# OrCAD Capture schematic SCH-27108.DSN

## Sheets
1 TITLE PAGE: title: 1231X-MRB  (Navajo); rev: A2; company: Freescale Semiconductor; note: SCH-27108 PDF: SPF-27108; note: 6501 William Cannon Drive West; note: Austin, TX 78735-8598
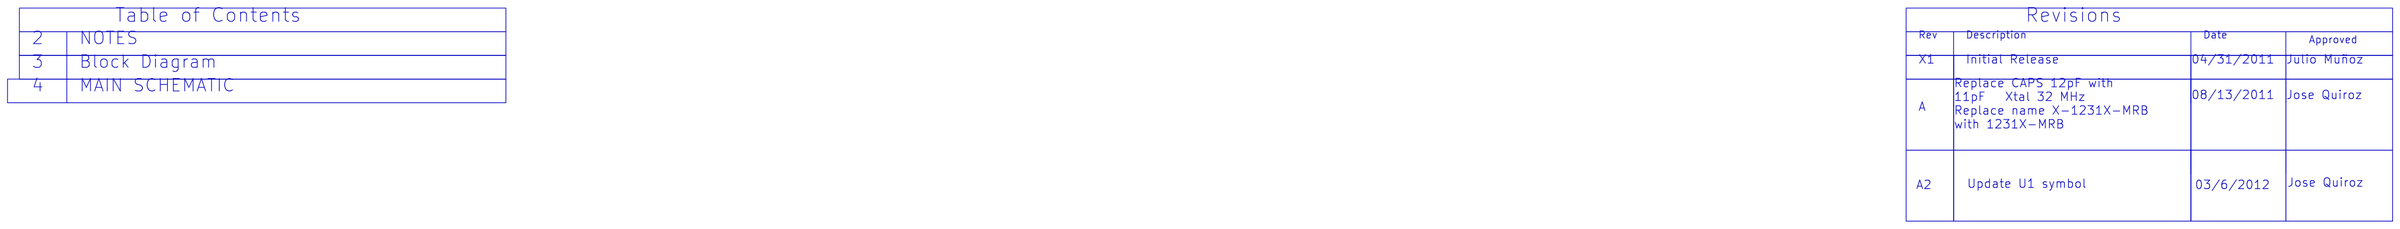
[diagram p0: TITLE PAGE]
2 NOTES
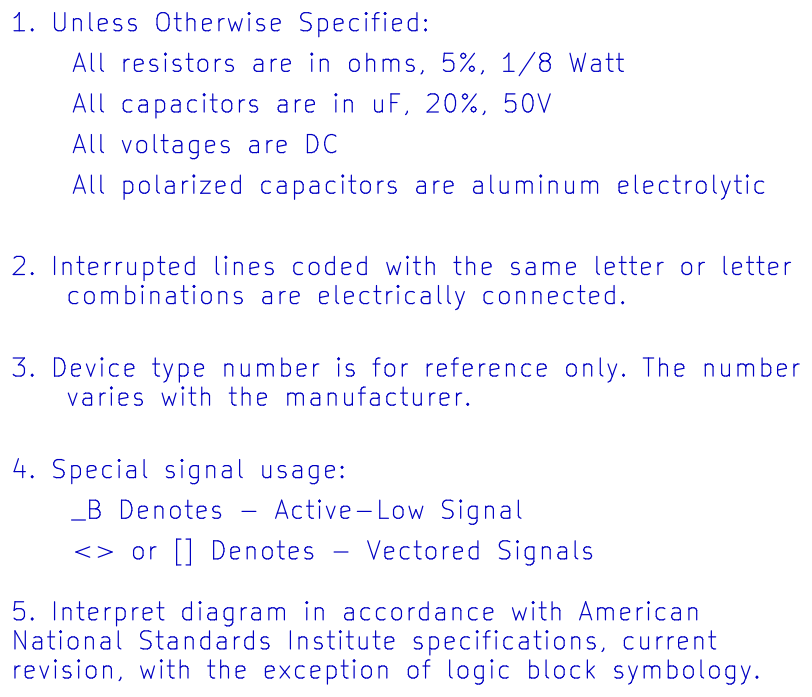
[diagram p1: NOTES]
3 Block Diagram
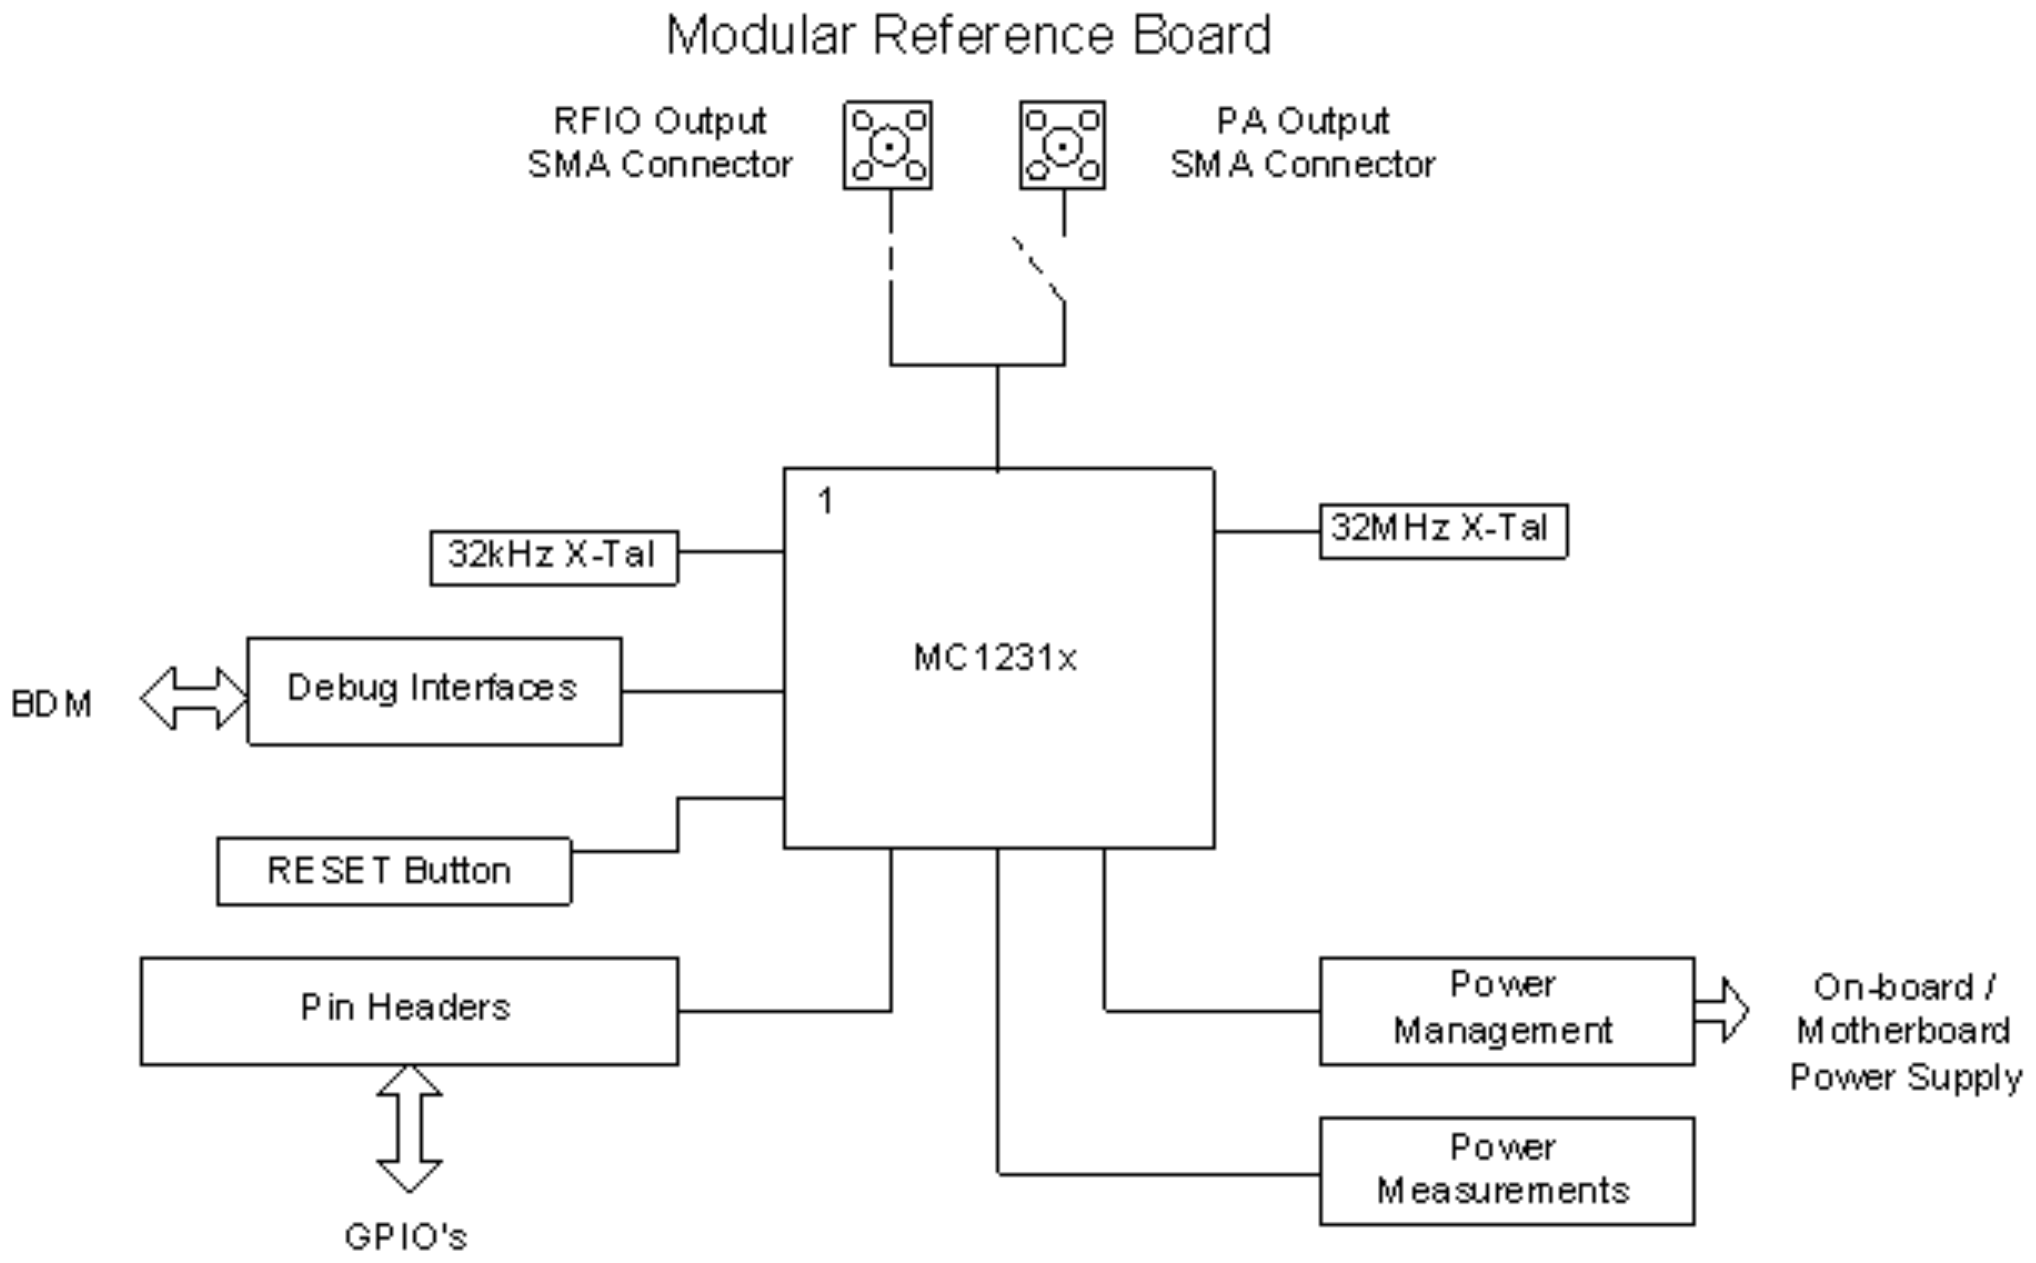
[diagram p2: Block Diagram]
4 MAIN SCHEMATIC: size C
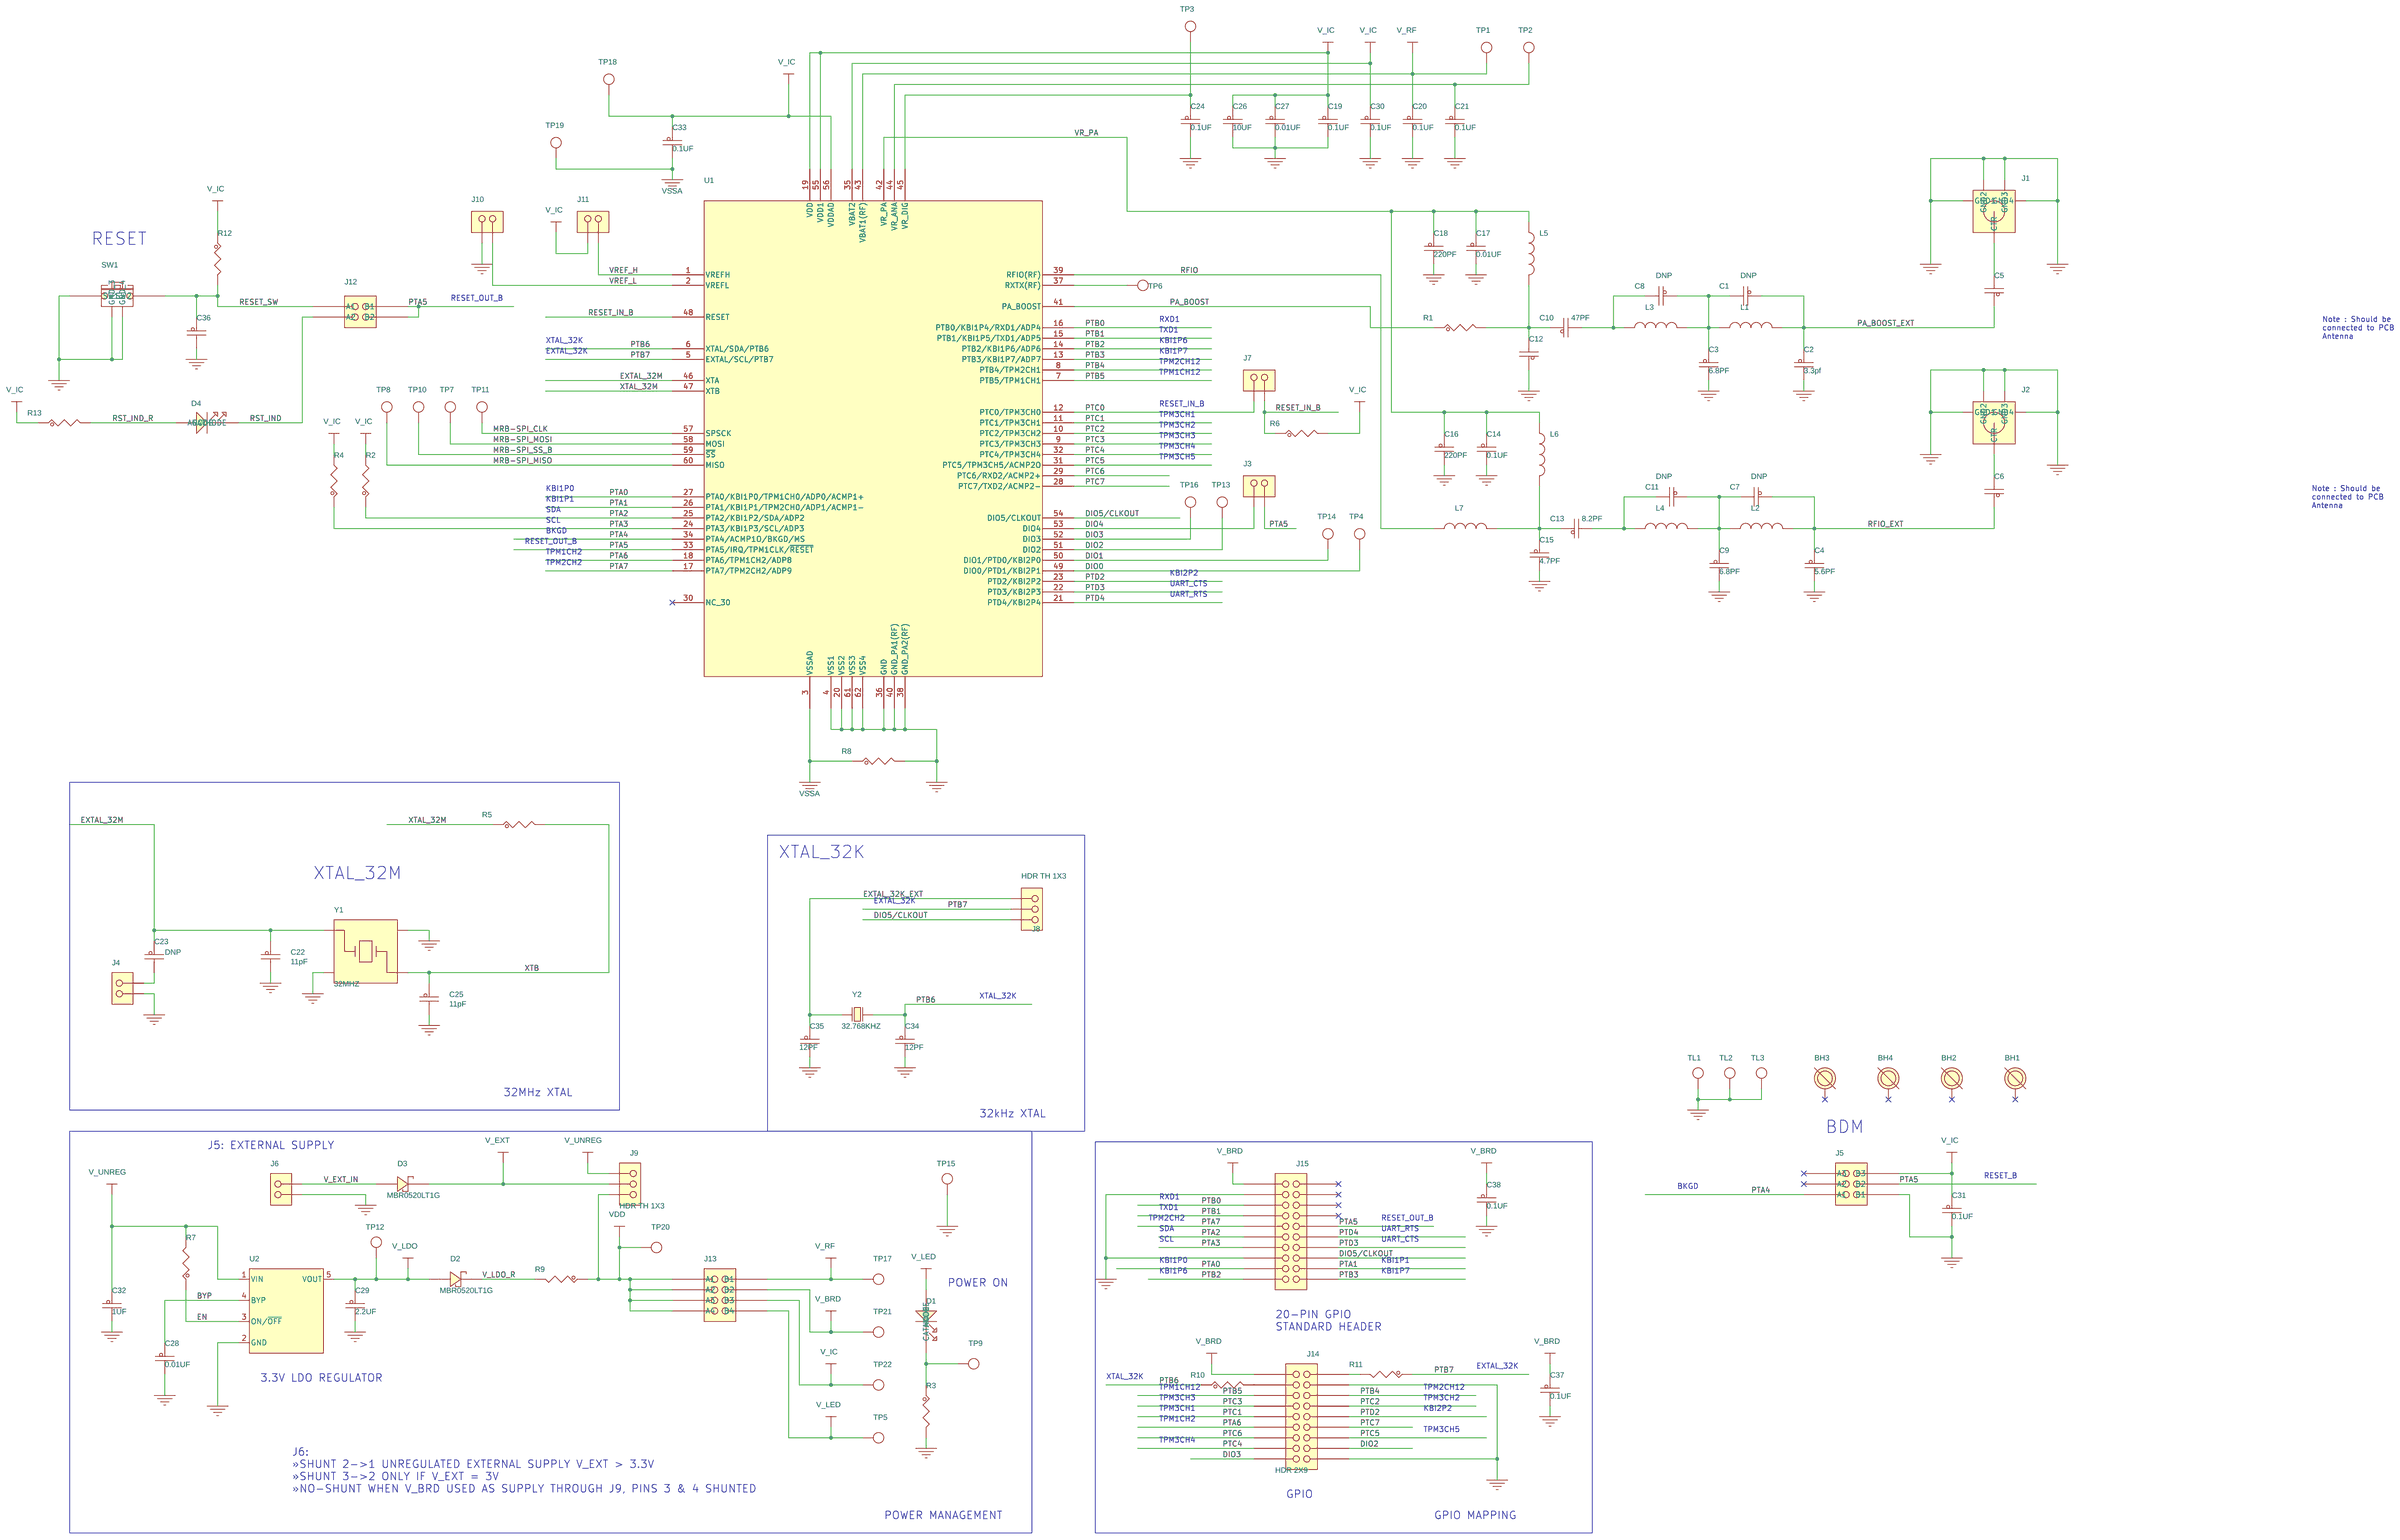
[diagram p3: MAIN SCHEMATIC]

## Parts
BH1  125  [MH125-160]
BH2  125  [MH125-160]
BH3  125  [MH125-160]
BH4  125  [MH125-160]
C1  10PF  [0402_CC]
C2  3.3pf  [0402_CC]
C3  6.8PF  [0402_CC]
C4  5.6PF  [0402_CC]
C5  10PF  [0402_CC]
C6  10PF  [0402_CC]
C7  10PF  [0402_CC]
C8  10PF  [0402_CC]
C9  6.8PF  [0402_CC]
C10  47PF  [0402_CC]
C11  10PF  [0402_CC]
C12  10PF  [0402_CC]
C13  8.2PF  [0402_CC]
C14  0.1UF  [0402_CC]
C15  4.7PF  [0402_CC]
C16  220PF  [0402_CC]
C17  0.01UF  [0402_CC]
C18  220PF  [0402_CC]
C19  0.1UF  [CC0402_25]
C20  0.1UF  [CC0402_25]
C21  0.1UF  [CC0402_25]
C22  11pF  [CC0402_25]
C23  10PF  [0402_CC]
C24  0.1UF  [CC0402_25]
C25  11pF  [CC0402_25]
C26  10UF  [CC0805_OV]
C27  0.01UF  [CC0402_25]
C28  0.01UF  [CC0402_25]
C29  2.2UF  [CC0603_OV]
C30  0.1UF  [CC0402_25]
C31  0.1UF  [CC0402_25]
C32  1UF  [CC0603_OV]
C33  0.1UF  [CC0402_25]
C34  12PF  [CC0402_25]
C35  12PF  [CC0402_25]
C36  1000pF  [CC0402_25]
C37  0.1UF  [CC0402_25]
C38  0.1UF  [CC0402_25]
D1  GREEN  [led2_0805]
D2  MBR0520LT1G  [SOD123]
D3  MBR0520LT1G  [SOD123]
D4  RED  [led2_0805]
J1  CON_1_SMA  [CON_SMA_8363]
J2  CON_1_SMA  [CON_SMA_8363]
J3  HDR 1X2  [hdr102]
J4  HDR 1X2  [hdr102]
J5  HDR 2X3  [HDR203]
J6  HDR 1X2  [hdr102]
J7  HDR 1X2  [hdr102]
J8  HDR TH 1X3  [HDR103]
J9  HDR TH 1X3  [HDR103]
J10  HDR 1X2  [hdr102]
J11  HDR 1X2  [hdr102]
J12  961204-6404-AR  [hdr202_100_th]
J13  HDR_2X4  [HDR2X4]
J14  HDR 2X9  [hdr_9x2_tsw_mirrored]
J15  HDR_10X2  [hdr210_mirrored]
L1  5.6NH  [0402_CC]
L2  6.8nH  [0402_CC]
L3  5.6NH  [0402_CC]
L4  6.8nH  [0402_CC]
L5  33nH  [0402_CC]
L6  33nH  [0402_CC]
L7  0.0039UH  [0402_CC]
R1  0  [0402_CC]
R2  4.7K  [RC0603_OV]
R3  330  [RC0402_25]
R4  4.7K  [RC0603_OV]
R5  0  [RC0603_OV]
R6  10.0K  [RC0402_25]
R7  0  [RC0603_OV]
R8  0  [RC0603_OV]
R9  0  [RC0603_OV]
R10  0  [RC0603_OV]
R11  0  [RC0603_OV]
R12  15K  [RC0402_25]
R13  422.0  [RC0603_OV]
SW1  SW_MOM  [sw_tact_skqy]
TL1  TESTLOOP  [testpoint_135_070mil]
TL2  TESTLOOP  [testpoint_135_070mil]
TL3  TESTLOOP  [testpoint_135_070mil]
TP1  TPAD_040  [TPAD_040]
TP2  TPAD_040  [TPAD_040]
TP3  TPAD_040  [TPAD_040]
TP4  TPAD_040  [TPAD_040]
TP5  TPAD_040  [TPAD_040]
TP6  TPAD_040  [TPAD_040]
TP7  TPAD_040  [TPAD_040]
TP8  TPAD_040  [TPAD_040]
TP9  TPAD_040  [TPAD_040]
TP10  TPAD_040  [TPAD_040]
TP11  TPAD_040  [TPAD_040]
TP12  TPAD_040  [TPAD_040]
TP13  TPAD_040  [TPAD_040]
TP14  TPAD_040  [TPAD_040]
TP15  TPAD_040  [TPAD_040]
TP16  TPAD_040  [TPAD_040]
TP17  TPAD_040  [TPAD_040]
TP18  TPAD_040  [TPAD_040]
TP19  TPAD_040  [TPAD_040]
TP20  TPAD_040  [TPAD_040]
TP21  TPAD_040  [TPAD_040]
TP22  TPAD_040  [TPAD_040]
U1  MC12311  [LGA60_0P5_8X8]
U2  LP2985AIM5-3.3  [SOT-23-5]
Y1  32MHZ  [xtlosc4_3p2x2p5mm_sm]
Y2  32.768KHZ  [XTAL2-3p2x1p5-SM]

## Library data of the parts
BH1-BH4 = MOUNT_HOLE: NON-PLATED MOUNTING HOLE 125 DRILL / 160 KEEPOUT NO PART TO ORDER; AGILE_PN: 510-75297; CAD_APPROVED: Yes; HEIGHT: 0.1 MM; ROHS: Yes
C1 C7 C8 C11 C23 = CAP_NP: CAP CER 10PF 50V 5% C0G 0402; AGILE_PN: 150-75265; ASSY_OPT: DNP; CAD_APPROVED: YES; FPLIST: CC0402_25,CC0402_HD,0402_CC; HEIGHT: 0.635MM; MFG_NAME01: AVX; MFG_PN01: 04025A100JAT2A; ROHS: Yes; TOL: 5%; Tolerance: 5%
C2 = CAP_NP: CAP CER 3.3PF 25V 0.1PF -- 0402; AGILE_PN: 150-78484; CAD_APPROVED: Yes; FPLIST: CC0402_25,CC0402_HD,0402_CC; HEIGHT: 0.5MM; MFG_NAME01: AVX; MFG_PN01: 04023J3R3BBSTR; ROHS: Yes
C3 C9 = CAP_NP: CAP CER 6.8PF 50V 0.5PF C0G 0402; AGILE_PN: 150-30300; CAD_APPROVED: Yes; FPLIST: CC0402_25,CC0402_HD,0402_CC; HEIGHT: 0.55MM; MFG_NAME01: MURATA; MFG_PN01: GRM1555C1H6R8DZ01J; ROHS: Yes; Tolerance: 0.5PF %
C4 = CAP_NP: CAP CER 5.6PF 50V +/-0.25PF C0G CC0402; AGILE_PN: 150-75521; CAD_APPROVED: Yes; FPLIST: CC0402_25,CC0402_HD,0402_CC; HEIGHT: 0.55MM; MFG_NAME01: MURATA; MFG_PN01: GJM1555C1H5R6CB01D; ROHS: Yes; Tolerance: 0.25PF
C5 C6 C12 = CAP_NP: CAP CER 10PF 50V 5% C0G 0402; AGILE_PN: 150-75265; CAD_APPROVED: YES; FPLIST: CC0402_25,CC0402_HD,0402_CC; HEIGHT: 0.635MM; MFG_NAME01: AVX; MFG_PN01: 04025A100JAT2A; ROHS: Yes; TOL: 5%; Tolerance: 5%
C10 = CAP_NP: CAP CER 47PF 50V 5% C0G 0402; AGILE_PN: 150-75169; CAD_APPROVED: Yes; FPLIST: CC0402_25,CC0402_HD,0402_CC; HEIGHT: 0.64 MM; MFG_NAME01: CAL-CHIP; MFG_PN01: GMC04CG470J50NT-LF; ROHS: Yes; Tolerance: 5%
C13 = CAP_NP: CAP CER 8.2PF 50V 0.25PF C0G 0402; AGILE_PN: 150-30084; CAD_APPROVED: Yes; FPLIST: CC0402_25,CC0402_HD,0402_CC; HEIGHT: 0.56MM; MFG_NAME01: AVX; MFG_PN01: 04025A8R2CAT2A; ROHS: Yes; Tolerance: 0.25PF
C14 C19-C21 C24 C30 C31 C33 C37 C38 = CAP_NP: CAP CER 0.1UF 16V 10% X7R 0402; AGILE_PN: 150-75182; CAD_APPROVED: Yes; FPLIST: CC0402_25,CC0402_HD,0402_CC; HEIGHT: 0.635MM; MFG_NAME01: KEMET; MFG_PN01: C0402C104K4RAC; ROHS: Yes; Tolerance: 10%
C15 = CAP_NP: CAP CER 4.7PF 50V 0.25PF C0G 0402; AGILE_PN: 150-76335; CAD_APPROVED: Yes; FPLIST: CC0402_25,CC0402_HD,0402_CC; HEIGHT: 0.55MM; MFG_NAME01: MURATA; MFG_PN01: GRM1555C1H4R7CA01D; ROHS: Yes; Tolerance: 0.25pF
C16 C18 = CAP_NP: CAP CER 220PF 50V 5% C0G 0402; AGILE_PN: 150-30297; CAD_APPROVED: Yes; FPLIST: CC0402_25,CC0402_HD,0402_CC; HEIGHT: 0.55MM; MFG_NAME01: KEMET; MFG_PN01: C0402C221J5GAC; ROHS: Yes; Tolerance: 5%
C17 C27 C28 = CAP_NP: CAP CER 0.01UF 50V 10% X7R 0402; AGILE_PN: 150-30114; CAD_APPROVED: Yes; FPLIST: CC0402_25,CC0402_HD,0402_CC; HEIGHT: 0.74 MM; MFG_NAME01: MURATA; MFG_PN01: GCM155R71H103KA55D; ROHS: Yes; Tolerance: 10%
C22 C25 = CAP_NP: CAP CER 11pF 50V 5% C0G 0402; AGILE_PN: 150-78794; CAD_APPROVED: Yes; FPLIST: CC0402_25,CC0402_HD,0402_CC; HEIGHT: 0.55MM; MFG_NAME01: TDK; MFG_PN01: C1005C0G1H110J; ROHS: Yes; Tolerance: 5%
C26 = CAP_NP: CAP CER 10UF 10V 10% X5R 0805; AGILE_PN: 150-75204; CAD_APPROVED: Yes; FPLIST: CC0805_OV,CC0805,0805_CC; HEIGHT: 1.6MM; MFG_NAME01: MURATA; MFG_PN01: GRM21BR61A106KE19_; ROHS: Yes; Tolerance: 10%
C29 = CAP_NP: CAP CER 2.2UF 10V 10% X7R 0603; AGILE_PN: 150-78564; CAD_APPROVED: Yes; FPLIST: CC0603_OV,CC0603,0603_CC; HEIGHT: 1.25MM; MFG_NAME01: MURATA; MFG_PN01: GRM188R71A225KE15D; ROHS: Yes; Tolerance: 10%
C32 = CAP_NP: CAP CER 1.0UF 10V 10% X7R 0603; AGILE_PN: 150-78462; CAD_APPROVED: Yes; FPLIST: CC0603_OV,CC0603,0603_CC; HEIGHT: 0.9MM; MFG_NAME01: MURATA; MFG_PN01: GRM188R71A105KA61D; ROHS: Yes; Tolerance: 10%
C34 C35 = CAP_NP: CAP CER 12PF 50V 5% C0G 0402; AGILE_PN: 150-75680; CAD_APPROVED: Yes; FPLIST: CC0402_25,CC0402_HD,0402_CC; HEIGHT: 0.55MM; MFG_NAME01: MURATA; MFG_PN01: GRM1555C1H120JZ01D; ROHS: Yes; Tolerance: 5%
C36 = CAP_NP: CAP CER 1000PF 50V 5% C0G 0402; AGILE_PN: 150-76334; CAD_APPROVED: Yes; FPLIST: CC0402_25,CC0402_HD,0402_CC; HEIGHT: 0.55MM; MFG_NAME01: MURATA; MFG_PN01: GRM1555C1H102JA01D; ROHS: Yes; Tolerance: 5%
D1 = LED: LED GRN SGL 30MA SMT 0805; AGILE_PN: 370-76462; CAD_APPROVED: Yes; HEIGHT: 0.9MM; MFG_NAME01: LITE ON; MFG_PN01: LTST-C171KGKT; ROHS: Yes
D2 D3 = DIODE_SCHTKY: DIODE SCH 0.5A 20V SOD-123; AGILE_PN: 480-75176; CAD_APPROVED: Yes; HEIGHT: 1.45MM; MFG_NAME01: ON SEMICONDUCTOR; ROHS: Yes
D4 = LED: LED RED CLEAR SGL 30MA SMT 0805; AGILE_PN: 370-76461; CAD_APPROVED: Yes; HEIGHT: 0.9MM; MFG_NAME01: LITE ON; MFG_PN01: LTST-C171KRKT; ROHS: Yes
J1 J2 = CON5_SMA_MMCX: CON 1 COAX SMA SKT TH -- 376H AU; AGILE_PN: 210-75870; CAD_APPROVED: Yes; HEIGHT: 9.55MM; MFG_NAME01: SAMTEC; MFG_PN01: SMA-J-P-H-ST-TH1; ROHS: Yes
J3 J4 J6 J7 J10 J11 = CONN_HDR_2X1: HDR 1X2 TH 100MIL SP 330H SN 115L; AGILE_PN: 210-76752; CAD_APPROVED: Yes; HEIGHT: 8.58MM; MFG_NAME01: Samtec; MFG_PN01: TSW-102-23-T-S; ROHS: Yes
J5 = CONN_HDR_3X2: HDR 2X3 TH 100MIL CTR 335H AU 95L; AGILE_PN: 210-75698; CAD_APPROVED: Yes; HEIGHT: 8.5MM; MFG_NAME01: SAMTEC; MFG_PN01: TSW-103-07-S-D; ROHS: Yes
J8 J9 = CONN_HDR_3X1: HDR 1X3 TH 100MIL SP 339H AU 100L; AGILE_PN: 210-75726; CAD_APPROVED: Yes; HEIGHT: 8.65MM; MFG_NAME01: SAMTEC; MFG_PN01: TSW-103-07-G-S; ROHS: Yes
J12 = CONN_HDR_2X2: HDR 2X2 TH 100MIL CTR 323H AU 130L; AGILE_PN: 210-79741; CAD_APPROVED: Yes; HEIGHT: 8.2MM; MFG_NAME01: 3M; ROHS: Yes
J13 = CONN_HDR_4X2: HDR 2X4 TH 100MIL CTR 330H AU 100L; AGILE_PN: 210-75541; CAD_APPROVED: Yes; HEIGHT: 8.6MM; MFG_NAME01: SAMTEC; MFG_PN01: TSW-104-07-S-D; ROHS: Yes
J14 = CONN_HDR_9X2: HDR 2X9 TH 100MIL CTR 330H AU; AGILE_PN: 210-11415-09; CAD_APPROVED: Yes; FPLIST: hdr_9x2_tsw,hdr_9x2_tsw_mirrored; HEIGHT: 8.6MM; MFG_NAME01: SAMTEC; MFG_PN01: TSW-109-07-S-D; ROHS: Yes
J15 = CONN_HDR_10X2: HDR 2X10 TH 100MIL CTR 330H AU 100L; AGILE_PN: 210-76001; CAD_APPROVED: Yes; FPLIST: hdr210,hdr210_mirrored; HEIGHT: 8.71 MM; MFG_NAME01: SAMTEC; MFG_PN01: TSW-110-07-S-D; ROHS: Yes
L1 L3 = INDUCTOR: IND -- 0.0056UH@100MHZ 300MA 0402; AGILE_PN: 180-75101; CAD_APPROVED: Yes; FPLIST: IND_0402,0402_CC; HEIGHT: 0.55MM; MFG_NAME01: TOKO INC.; MFG_PN01: LL1005-FHL5N6S; ROHS: Yes; Tolerance: 0.3NH
L2 L4 = INDUCTOR: IND -- 0.0068UH@100MHZ 400MA 5% 0402; AGILE_PN: 180-75396; CAD_APPROVED: Yes; FPLIST: IND_0402,0402_CC; HEIGHT: 0.55 MM; MFG_NAME01: TOKO INC.; MFG_PN01: LL1005-FHL6N8J; ROHS: Yes; Tolerance: 5%
L5 L6 = INDUCTOR: IND -- 0.033UH@100MHZ 200MA 5% 0402; AGILE_PN: 180-75099; CAD_APPROVED: YES; FPLIST: IND_0402,0402_CC; HEIGHT: 0.55MM; MFG_NAME01: TOKO INC.; MFG_PN01: LL1005-FHL33NJ; ROHS: Yes; Tolerance: 5%
L7 = INDUCTOR: IND -- 0.0039UH@100MHZ 300MA +/-0.3NH 0402; AGILE_PN: 180-30073; CAD_APPROVED: Yes; FPLIST: IND_0402,0402_CC; HEIGHT: 0.60mm; MFG_NAME01: MURATA; MFG_PN01: LQG15HN3N9S02D; ROHS: Yes
R1 = RES: RES MF ZERO OHM 1/10W -- 0402; AGILE_PN: 470-79965; CAD_APPROVED: Yes; FPLIST: RC0402_25,RC0402_HD,RC0402_X2,0402_CC; MFG_NAME01: Panasonic; MFG_PN01: ERJ-2GE0R00X; ROHS: Yes
R2 R4 = RES: RES MF 4.7K 1/10W 5% 0603; AGILE_PN: 470-75414; CAD_APPROVED: Yes; FPLIST: RC0603_OV,RC0603,0603_CC; MFG_NAME01: VISHAY INTERTECHNOLOGY; MFG_PN01: CRCW06034K70JNEA; ROHS: Yes; Tolerance: 5%
R3 = RES: RES MF 330 OHM 1/16W 5% 0402; AGILE_PN: 470-75613; CAD_APPROVED: Yes; FPLIST: RC0402_25,RC0402_HD,0402_CC; MFG_NAME01: VISHAY INTERTECHNOLOGY; MFG_PN01: CRCW0402330RJNED; ROHS: Yes; Tolerance: 5%
R5 R7-R11 = RES: RES MF ZERO OHM 1/10W -- 0603; AGILE_PN: 470-75407; CAD_APPROVED: Yes; FPLIST: RC0603_OV,RC0603,R603-X2,0603_CC; MFG_NAME01: VISHAY INTERTECHNOLOGY; MFG_PN01: CRCW06030000Z0EA; ROHS: Yes; Tolerance: 1%
R6 = RES: RES MF 10.0K 1/16W 1% 0402; AGILE_PN: 470-75416; CAD_APPROVED: Yes; FPLIST: RC0603_OV,RC0603,0603_CC; MFG_NAME01: VISHAY INTERTECHNOLOGY; MFG_PN01: CRCW040210K0FKED; ROHS: Yes; Tolerance: 1%
R12 = RES: RES MF 15K 1/16W 5% 0402; AGILE_PN: 470-30313; CAD_APPROVED: Yes; FPLIST: RC0402_25,RC0402_HD,0402_CC; HEIGHT: 0.41mm; MFG_NAME01: VISHAY INTERTECHNOLOGY; MFG_PN01: CRCW040215K0JNED; ROHS: Yes; TOL: 5%; Tolerance: %5
R13 = RES: RES MF 422 OHM  1/10W 1% 0603; AGILE_PN: 470-77949; CAD_APPROVED: Yes; FPLIST: RC0603_OV,RC0603,0603_CC; MFG_NAME01: YAGEO AMERICA; MFG_PN01: RC0603FR-07422RL; ROHS: Yes; Tolerance: 1%
SW1 = SW2_STM151: SW SPST MOM PB 50MA 12V SMT; AGILE_PN: 510-77653; CAD_APPROVED: Yes; HEIGHT: 2.5MM; MFG_NAME01: ALPS ELECTRIC (USA) INC.; MFG_PN01: SKQYPDE010; ROHS: Yes
TL1-TL3 = TestLoop: TEST POINT PAD SIZE 3.4MM X 1.8MM SMT; AGILE_PN: 211-75906; CAD_APPROVED: Yes; FPLIST: testpoint_135_070mil,testpoint_110_045mil,testpoint_125x40milmod; HEIGHT: 1.53 MM; MFG_NAME01: KEYSTONE ELECTRONICS; MFG_PN01: 5015; ROHS: Yes
TP1-TP22 = TestLoop: TEST POINT PAD 40MIL DIA SMT, NO PART TO ORDER; AGILE_PN: 211-76643; CAD_APPROVED: Yes; HEIGHT: 0.1MM; MFG_NAME01: NOTACOMPONENT; MFG_PN01: NOTACOMPONENT; ROHS: Yes
U1 = MC12311_LGA_60P: IC MCU 8BIT 32KB FLASH 2KB RAM 50MHZ 1.8-3.6V LGA60; AGILE_PN: 344-01203; CAD_APPROVED: Yes; HEIGHT: 0.98MM; MFG_NAME01: Freescale Semiconductor; MFG_PN01: MC12311CHN; ROHS: Yes
U2 = LP2992X_5P: IC VREG LDO 3.3V 150MA 3.8-16V SOT-23-5; AGILE_PN: 312-79597; CAD_APPROVED: Yes; HEIGHT: 1.22 MM; MFG_NAME01: NATIONAL SEMICONDUCTOR; MFG_PN01: LP2985AIM5-3.3/NOPB; ROHS: Yes
Y1 = XTAL_13Y: XTAL 32MHZ 9PF -- SMT 3.2X2.5MM; AGILE_PN: 230-77690; CAD_APPROVED: Yes; HEIGHT: 0.8MM; MFG_NAME01: NDK; MFG_PN01: EXS00A-CS02368; ROHS: Yes
Y2 = CRYSTAL: XTAL 32.768KHZ SMT ROHS COMPLIANT; AGILE_PN: 230-76374; CAD_APPROVED: Yes; HEIGHT: 0.9MM; MFG_NAME01: EPSON ELECTRONICS; MFG_PN01: FC-135 32.7680KA-A3; ROHS: Yes

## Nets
GND: C2.2 C3.2 C4.2 C9.2 C12.1 C14.2 C15.2 C16.2 C17.2 C18.2 C19.2 C20.2 C21.2 C22.2 C24.2 C25.2 C26.2 C27.2 C28.2 C29.2 C30.2 C31.2 C32.2 C34.2 C35.2 C36.2 C37.2 C38.2 J1.2(GND1) J1.3(GND2) J1.4(GND3) J1.5(GND4) J2.2(GND1) J2.3(GND2) J2.4(GND3) J2.5(GND4) J4.2 J5.2(B1) J6.2 J10.2 J14.4 J14.18 J15.3 J15.15 R3.2 R8.2 SW1.1(SW1) SW1.3(GND) SW1.4(GND) TL1.1(Pin1) TL2.1(Pin1) TL3.1(Pin1) TP15.1(Pin1) U1.4(VSS1) U1.20(VSS2) U1.36(GND) U1.38(GND_PA2(RF)) U1.40(GND_PA1(RF)) U1.61(VSS3) U1.62(VSS4) U2.2(GND) Y1.2 Y1.4
VDD: J9.3 J13.1(A1) J13.3(A2) J13.5(A3) J13.7(A4) R9.1 TP20.1(Pin1)
VSSA: C33.2 R8.1 TP19.1(Pin1) U1.3(VSSAD)
BYP: C28.1 U2.4(BYP)
DIO0: TP4.1(Pin1) U1.49(DIO0/PTD1/KBI2P1)
DIO1: TP14.1(Pin1) U1.50(DIO1/PTD0/KBI2P0)
DIO2: J14.16 TP13.1(Pin1) U1.51(DIO2)
DIO3: J14.17 TP16.1(Pin1) U1.52(DIO3)
DIO4: J3.2 U1.53(DIO4)
DIO5/CLKOUT: J8.1 J15.16 U1.54(DIO5/CLKOUT)
EN: R7.1 U2.3(ON/~{OFF})
EXTAL_32K_EXT: C35.1 J8.3 Y2.1
EXTAL_32M: C22.1 C23.1 U1.46(XTA) Y1.1
MRB-SPI_CLK: TP11.1(Pin1) U1.57(SPSCK)
MRB-SPI_MISO: TP8.1(Pin1) U1.60(MISO)
MRB-SPI_MOSI: TP7.1(Pin1) U1.58(MOSI)
MRB-SPI_SS_B: TP10.1(Pin1) U1.59(~{SS})
PA_BOOST: R1.1 U1.41(PA_BOOST)
PA_BOOST_EXT: C1.1 C2.1 C5.1 L1.2
PTA0: J15.17 U1.27(PTA0/KBI1P0/TPM1CH0/ADP0/ACMP1+)
PTA1: J15.18 U1.26(PTA1/KBI1P1/TPM2CH0/ADP1/ACMP1-)
PTA2: J15.11 R2.1 U1.25(PTA2/KBI1P2/SDA/ADP2)
PTA3: J15.13 R4.1 U1.24(PTA3/KBI1P3/SCL/ADP3)
PTA4: J5.1(A1) U1.34(PTA4/ACMP1O/BKGD/MS)
PTA5: J3.1 J5.4(B2) J12.2(B1) J12.4(B2) J15.10 U1.33(PTA5/IRQ/TPM1CLK/~{RESET})
PTA6: J14.11 U1.18(PTA6/TPM1CH2/ADP8)
PTA7: J15.9 U1.17(PTA7/TPM2CH2/ADP9)
PTB0: J15.5 U1.16(PTB0/KBI1P4/RXD1/ADP4)
PTB1: J15.7 U1.15(PTB1/KBI1P5/TXD1/ADP5)
PTB2: J15.19 U1.14(PTB2/KBI1P6/ADP6)
PTB3: J15.20 U1.13(PTB3/KBI1P7/ADP7)
PTB4: J14.6 U1.8(PTB4/TPM2CH1)
PTB5: J14.5 U1.7(PTB5/TPM1CH1)
PTB6: C34.1 R10.1 U1.6(XTAL/SDA/PTB6) Y2.2
PTB7: J8.2 R11.1 U1.5(EXTAL/SCL/PTB7)
PTC0: J7.2 U1.12(PTC0/TPM3CH0)
PTC1: J14.9 U1.11(PTC1/TPM3CH1)
PTC2: J14.8 U1.10(PTC2/TPM3CH2)
PTC3: J14.7 U1.9(PTC3/TPM3CH3)
PTC4: J14.15 U1.32(PTC4/TPM3CH4)
PTC5: J14.14 U1.31(PTC5/TPM3CH5/ACMP2O)
PTC6: J14.13 U1.29(PTC6/RXD2/ACMP2+)
PTC7: J14.12 U1.28(PTC7/TXD2/ACMP2-)
PTD2: J14.10 U1.23(PTD2/KBI2P2)
PTD3: J15.14 U1.22(PTD3/KBI2P3)
PTD4: J15.12 U1.21(PTD4/KBI2P4)
RESET_IN_B: J7.1 R6.1 U1.48(RESET)
RESET_SW: C36.1 J12.1(A1) R12.2 SW1.2(SW2)
RFIO: L7.1 U1.39(RFIO(RF))
RFIO_EXT: C4.1 C6.1 C7.1 L2.2
RST_IND: D4.C(CATHODE) J12.3(A2)
RST_IND_R: D4.A(ANODE) R13.2
V_BRD: C37.1 C38.1 J13.4(B2) J14.1 J15.1 TP21.1(Pin1)
V_EXT: D3.C J9.2
V_EXT_IN: D3.A J6.1
V_IC: C19.1 C26.1 C27.1 C30.1 C31.1 C33.1 J5.6(B3) J11.2 J13.6(B3) R2.2 R4.2 R6.2 R12.1 R13.1 TP18.1(Pin1) TP22.1(Pin1) U1.19(VDD) U1.35(VBAT2) U1.55(VDD1) U1.56(VDDAD)
V_LDO: C29.1 D2.A TP12.1(Pin1) U2.5(VOUT)
V_LDO_R: D2.C R9.2
V_LED: D1.A(ANODE) J13.8(B4) TP5.1(Pin1)
V_RF: C20.1 J13.2(B1) TP1.1(Pin1) TP17.1(Pin1) U1.43(VBAT1(RF))
V_UNREG: C32.1 J9.1 R7.2 U2.1(VIN)
VR_PA: C14.1 C16.1 C17.1 C18.1 L5.1 L6.1 U1.42(VR_PA)
VREF_H: J11.1 U1.1(VREFH)
VREF_L: J10.1 U1.2(VREFL)
XTAL_32M: R5.1 U1.47(XTB)
XTB: C25.1 R5.2 Y1.3
N20191226: D1.C(CATHODE) R3.1 TP9.1(Pin1)
N21047783: C23.2 J4.1
N22295892: C21.1 TP2.1(Pin1) U1.44(VR_ANA)
N22301222: C24.1 TP3.1(Pin1) U1.45(VR_DIG)
N22363297: C10.1 C12.2 L5.2 R1.2
N22372226: C8.2 C10.2 L3.1
N22374694: C1.2 C3.1 C8.1 L1.1 L3.2
N22385169: C7.2 C9.1 C11.1 L2.1 L4.2
N22385173: C13.1 C15.1 L6.2 L7.2
N22385175: C11.2 C13.2 L4.1
N22485610: J14.2 R11.2
N22661201: TP6.1(Pin1) U1.37(RXTX(RF))
N22828056: C5.2 J1.1(CTR)
N22834395: C6.2 J2.1(CTR)
N23059382: J14.3 R10.2

Not connected (* = marked no-connect by the designer): BH1 1*; BH2 1*; BH3 1*; BH4 1*; J5 3(A2)* 5(A3)*; J15 2* 4* 6* 8*; U1 30(NC)*

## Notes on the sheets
sheet 1
- Table of Contents
- Revisions
- 2
- NOTES
- Rev
- Description
- Date
- Approved
- 3
- Block Diagram
- X1
- Initial Release
- 04/31/2011
- Julio Muñoz
- 4
- MAIN SCHEMATIC
- Replace CAPS 12pF with
  11pF   Xtal 32 MHz
  Replace name X-1231X-MRB
  with 1231X-MRB
- 08/13/2011
- Jose Quiroz
- A
- A2
- Update U1 symbol
- 03/6/2012
- Jose Quiroz
sheet 2
- 1. Unless Otherwise Specified:
- All resistors are in ohms, 5%, 1/8 Watt
- All capacitors are in uF, 20%, 50V
- All voltages are DC
- All polarized capacitors are aluminum electrolytic
- 2. Interrupted lines coded with the same letter or letter
      combinations are electrically connected.
- 3. Device type number is for reference only. The number
      varies with the manufacturer.
- 4. Special signal usage:
- _B Denotes - Active-Low Signal
- <> or [] Denotes - Vectored Signals
- 5. Interpret diagram in accordance with American
  National Standards Institute specifications, current
  revision, with the exception of logic block symbology.
sheet 4
- RESET
- RESET_OUT_B
- RXD1
- Note : Should be
  connected to PCB
  Antenna
- TXD1
- XTAL_32K
- KBI1P6
- EXTAL_32K
- KBI1P7
- TPM2CH12
- TPM1CH12
- RESET_IN_B
- TPM3CH1
- TPM3CH2
- TPM3CH3
- TPM3CH4
- TPM3CH5
- KBI1P0
- Note : Should be
  connected to PCB
  Antenna
- KBI1P1
- SDA
- BKGD
- SCL
- RESET_OUT_B
- TPM1CH2
- TPM2CH2
- KBI2P2
- UART_CTS
- UART_RTS
- XTAL_32K
- XTAL_32M
- EXTAL_32K
- XTAL_32K
- 32MHz XTAL
- 32kHz XTAL
- BDM
- J5: EXTERNAL SUPPLY
- RESET_B
- BKGD
- RXD1
- TPM2CH2
- TXD1
- RESET_OUT_B
- SDA
- UART_RTS
- SCL
- UART_CTS
- KBI1P0
- KBI1P1
- KBI1P6
- KBI1P7
- POWER ON
- 20-PIN GPIO
  STANDARD HEADER
- EXTAL_32K
- 3.3V LDO REGULATOR
- XTAL_32K
- TPM1CH12
- TPM2CH12
- TPM3CH3
- TPM3CH2
- TPM3CH1
- KBI2P2
- TPM1CH2
- TPM3CH5
- TPM3CH4
- J6:
  »SHUNT 2->1 UNREGULATED EXTERNAL SUPPLY V_EXT > 3.3V
  »SHUNT 3->2 ONLY IF V_EXT = 3V
  »NO-SHUNT WHEN V_BRD USED AS SUPPLY THROUGH J9, PINS 3 & 4 SHUNTED
- GPIO
- POWER MANAGEMENT
- GPIO MAPPING
